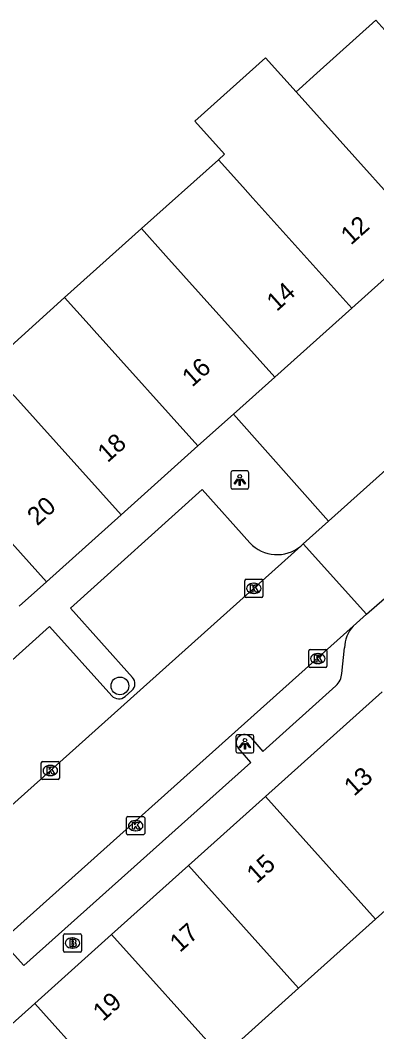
# Model space of a CAD drawing. Extents: x 162172 to 163187, y 382874 to 383684.
# Drawn here: x 162805.6 to 162825.2, y 383535.5 to 383591.4 of the extents above; entities that cross this region are included whole.
import ezdxf

# ---------------------------------------------------------------- set-up
doc = ezdxf.new("R2010")
doc.units = 0
for name, color, linetype in [('IMGEO_Boom', 7, 'Continuous'), ('IMGEO_Brandkraan', 7, 'Continuous'), ('IMGEO_Kolk', 7, 'Continuous'), ('IMGEO_Lichtpunt', 7, 'Continuous'), ('IMGEO_Pand', 7, 'Continuous'), ('IMGEO_Pand_nummerreeks', 7, 'Continuous'), ('IMGEO_Rijbaan_lokaal_open', 7, 'Continuous'), ('IMGEO_Voetpad_open', 7, 'Continuous')]:
    doc.layers.add(name, color=color, linetype=linetype)

msp = doc.modelspace()

# ---------------------------------------------------------------- linework, layer by layer
at = {"layer": 'IMGEO_Boom'}
msp.add_circle((162811.077, 383554.599), 0.489, dxfattribs=at)
at = {"layer": 'IMGEO_Brandkraan'}
for p, q in [((162807.957, 383539.978), (162807.957, 383540.83)), ((162808.032, 383540.904), (162808.884, 383540.904)), ((162808.445, 383540.684), (162808.47, 383540.684)), ((162808.958, 383540.83), (162808.958, 383539.978)), ((162808.468, 383540.124), (162808.443, 383540.124)), ((162808.884, 383539.904), (162808.032, 383539.904))]:
    msp.add_line(p, q, dxfattribs=at)
for points in [[(162807.957, 383539.978), (162807.957, 383540.83)], [(162808.032, 383540.904), (162808.884, 383540.904)], [(162808.958, 383540.83), (162808.958, 383539.978)], [(162808.305, 383540.604), (162808.305, 383540.204), (162808.518, 383540.204)], [(162808.536, 383540.604), (162808.305, 383540.604)], [(162808.484, 383540.523), (162808.43, 383540.523), (162808.43, 383540.447)], [(162808.43, 383540.447), (162808.483, 383540.447)], [(162808.492, 383540.371), (162808.43, 383540.371), (162808.43, 383540.29)], [(162808.43, 383540.29), (162808.492, 383540.29)], [(162808.884, 383539.904), (162808.032, 383539.904)]]:
    msp.add_lwpolyline(points, dxfattribs=at)
for centre, radius, start, end in [((162808.034, 383540.828), 0.0765, 91.552, 178.448), ((162808.034, 383540.828), 0.0765, 91.552, 178.448), ((162808.882, 383540.828), 0.0765, 1.552, 88.448), ((162808.882, 383540.828), 0.0765, 1.552, 88.448), ((162808.485, 383540.485), 0.0379, 267.8285, 90.9355), ((162808.493, 383540.33), 0.0404, 269.8759, 90.5077), ((162808.524, 383540.455), 0.251, 268.6676, 293.5347), ((162808.54, 383540.459), 0.145, 59.4692, 91.5367), ((162808.565, 383540.506), 0.0922, 285.5137, 58.1501), ((162808.57, 383540.314), 0.105, 301.3115, 78.989), ((162808.034, 383539.98), 0.0765, 181.552, 268.448), ((162808.034, 383539.98), 0.0765, 181.552, 268.448), ((162808.882, 383539.98), 0.0765, 271.552, 358.448), ((162808.882, 383539.98), 0.0765, 271.552, 358.448)]:
    msp.add_arc(centre, radius, start, end, dxfattribs=at)
for centre, major_axis, ratio, start_param, end_param in [((162808.444, 383540.404), (-0.387, 0.002), 0.722429, 4.712389, 7.853982), ((162808.469, 383540.404), (-0.39, 0.002), 0.717154, 1.570796, 4.712389)]:
    msp.add_ellipse(centre, major_axis=major_axis, ratio=ratio, start_param=start_param, end_param=end_param, dxfattribs=at)
at = {"layer": 'IMGEO_Kolk'}
for p, q in [((162817.97, 383559.558), (162817.97, 383560.41)), ((162818.045, 383560.484), (162818.897, 383560.484)), ((162818.458, 383560.264), (162818.483, 383560.264)), ((162818.971, 383560.41), (162818.971, 383559.558)), ((162818.481, 383559.704), (162818.456, 383559.704)), ((162818.897, 383559.484), (162818.045, 383559.484)), ((162821.5, 383555.683), (162821.5, 383556.535)), ((162821.575, 383556.609), (162822.427, 383556.609)), ((162821.988, 383556.389), (162822.013, 383556.389)), ((162822.501, 383556.535), (162822.501, 383555.683)), ((162822.011, 383555.829), (162821.986, 383555.829)), ((162822.427, 383555.609), (162821.575, 383555.609)), ((162806.737, 383549.503), (162806.737, 383550.355)), ((162806.812, 383550.429), (162807.664, 383550.429)), ((162807.225, 383550.209), (162807.25, 383550.209)), ((162807.738, 383550.355), (162807.738, 383549.503)), ((162807.248, 383549.649), (162807.223, 383549.649)), ((162807.664, 383549.429), (162806.812, 383549.429)), ((162811.52, 383547.384), (162812.372, 383547.384)), ((162811.445, 383546.458), (162811.445, 383547.31)), ((162811.933, 383547.164), (162811.958, 383547.164)), ((162812.446, 383547.31), (162812.446, 383546.458)), ((162812.372, 383546.384), (162811.52, 383546.384)), ((162811.956, 383546.604), (162811.931, 383546.604))]:
    msp.add_line(p, q, dxfattribs=at)
for points in [[(162817.97, 383559.558), (162817.97, 383560.41)], [(162818.045, 383560.484), (162818.897, 383560.484)], [(162818.291, 383560.184), (162818.414, 383560.184), (162818.414, 383560.033), (162818.544, 383560.184), (162818.708, 383560.184), (162818.562, 383560.033), (162818.715, 383559.784), (162818.563, 383559.784), (162818.478, 383559.948), (162818.414, 383559.881), (162818.414, 383559.784), (162818.291, 383559.784), (162818.291, 383560.184)], [(162818.971, 383560.41), (162818.971, 383559.558)], [(162818.897, 383559.484), (162818.045, 383559.484)], [(162821.5, 383555.683), (162821.5, 383556.535)], [(162821.575, 383556.609), (162822.427, 383556.609)], [(162821.821, 383556.309), (162821.944, 383556.309), (162821.944, 383556.158), (162822.074, 383556.309), (162822.238, 383556.309), (162822.092, 383556.158), (162822.245, 383555.909), (162822.093, 383555.909), (162822.008, 383556.073), (162821.944, 383556.006), (162821.944, 383555.909), (162821.821, 383555.909), (162821.821, 383556.309)], [(162822.501, 383556.535), (162822.501, 383555.683)], [(162822.427, 383555.609), (162821.575, 383555.609)], [(162806.737, 383549.503), (162806.737, 383550.355)], [(162806.812, 383550.429), (162807.664, 383550.429)], [(162807.738, 383550.355), (162807.738, 383549.503)], [(162807.058, 383550.129), (162807.181, 383550.129), (162807.181, 383549.978), (162807.311, 383550.129), (162807.475, 383550.129), (162807.329, 383549.978), (162807.482, 383549.729), (162807.33, 383549.729), (162807.245, 383549.893), (162807.181, 383549.826), (162807.181, 383549.729), (162807.058, 383549.729), (162807.058, 383550.129)], [(162807.664, 383549.429), (162806.812, 383549.429)], [(162811.52, 383547.384), (162812.372, 383547.384)], [(162811.445, 383546.458), (162811.445, 383547.31)], [(162811.766, 383547.084), (162811.889, 383547.084), (162811.889, 383546.933), (162812.019, 383547.084), (162812.183, 383547.084), (162812.037, 383546.933), (162812.19, 383546.684), (162812.038, 383546.684), (162811.953, 383546.848), (162811.889, 383546.781), (162811.889, 383546.684), (162811.766, 383546.684), (162811.766, 383547.084)], [(162812.446, 383547.31), (162812.446, 383546.458)], [(162812.372, 383546.384), (162811.52, 383546.384)]]:
    msp.add_lwpolyline(points, dxfattribs=at)
for centre, start, end in [((162818.047, 383560.408), 91.552, 178.448), ((162818.047, 383560.408), 91.552, 178.448), ((162818.895, 383560.408), 1.552, 88.448), ((162818.895, 383560.408), 1.552, 88.448), ((162818.047, 383559.56), 181.552, 268.448), ((162818.047, 383559.56), 181.552, 268.448), ((162818.895, 383559.56), 271.552, 358.448), ((162818.895, 383559.56), 271.552, 358.448), ((162821.577, 383556.533), 91.552, 178.448), ((162821.577, 383556.533), 91.552, 178.448), ((162822.425, 383556.533), 1.552, 88.448), ((162822.425, 383556.533), 1.552, 88.448), ((162821.577, 383555.685), 181.552, 268.448), ((162821.577, 383555.685), 181.552, 268.448), ((162822.425, 383555.685), 271.552, 358.448), ((162822.425, 383555.685), 271.552, 358.448), ((162806.814, 383550.353), 91.552, 178.448), ((162806.814, 383550.353), 91.552, 178.448), ((162807.662, 383550.353), 1.552, 88.448), ((162807.662, 383550.353), 1.552, 88.448), ((162806.814, 383549.505), 181.552, 268.448), ((162806.814, 383549.505), 181.552, 268.448), ((162807.662, 383549.505), 271.552, 358.448), ((162807.662, 383549.505), 271.552, 358.448), ((162811.522, 383547.308), 91.552, 178.448), ((162811.522, 383547.308), 91.552, 178.448), ((162812.37, 383547.308), 1.552, 88.448), ((162812.37, 383547.308), 1.552, 88.448), ((162811.522, 383546.46), 181.552, 268.448), ((162811.522, 383546.46), 181.552, 268.448), ((162812.37, 383546.46), 271.552, 358.448), ((162812.37, 383546.46), 271.552, 358.448)]:
    msp.add_arc(centre, 0.0765, start, end, dxfattribs=at)
for centre, major_axis, ratio, start_param, end_param in [((162818.457, 383559.984), (-0.387, 0.002), 0.722429, 4.712389, 7.853982), ((162818.482, 383559.984), (-0.39, 0.002), 0.717154, 1.570796, 4.712389), ((162821.987, 383556.109), (-0.387, 0.002), 0.722429, 4.712389, 7.853982), ((162822.012, 383556.109), (-0.39, 0.002), 0.717154, 1.570796, 4.712389), ((162807.224, 383549.929), (-0.387, 0.002), 0.722429, 4.712389, 7.853982), ((162807.249, 383549.929), (-0.39, 0.002), 0.717154, 1.570796, 4.712389), ((162811.932, 383546.884), (-0.387, 0.002), 0.722429, 4.712389, 7.853982), ((162811.957, 383546.884), (-0.39, 0.002), 0.717154, 1.570796, 4.712389)]:
    msp.add_ellipse(centre, major_axis=major_axis, ratio=ratio, start_param=start_param, end_param=end_param, dxfattribs=at)
at = {"layer": 'IMGEO_Lichtpunt'}
for p, q in [((162817.19, 383566.372), (162817.19, 383565.565)), ((162817.19, 383566.372), (162817.19, 383565.565)), ((162818.092, 383566.467), (162817.284, 383566.467)), ((162818.092, 383566.467), (162817.284, 383566.467)), ((162818.186, 383565.565), (162818.186, 383566.372)), ((162818.186, 383565.565), (162818.186, 383566.372)), ((162817.284, 383565.471), (162818.092, 383565.471)), ((162817.284, 383565.471), (162818.092, 383565.471)), ((162818.38, 383551.9), (162817.572, 383551.9)), ((162818.38, 383551.9), (162817.572, 383551.9)), ((162817.478, 383551.805), (162817.478, 383550.998)), ((162817.478, 383551.805), (162817.478, 383550.998)), ((162818.474, 383550.998), (162818.474, 383551.805)), ((162818.474, 383550.998), (162818.474, 383551.805)), ((162817.572, 383550.904), (162818.38, 383550.904)), ((162817.572, 383550.904), (162818.38, 383550.904))]:
    msp.add_line(p, q, dxfattribs=at)
for points in [[(162817.564, 383566.036), (162817.603, 383566.008), (162817.415, 383565.746), (162817.377, 383565.773), (162817.564, 383566.036)], [(162817.666, 383565.988), (162817.713, 383565.988), (162817.713, 383565.666), (162817.666, 383565.666), (162817.666, 383565.988)], [(162817.776, 383566.008), (162817.814, 383566.035), (162818.001, 383565.773), (162817.962, 383565.745), (162817.776, 383566.008)], [(162817.852, 383551.469), (162817.891, 383551.441), (162817.703, 383551.179), (162817.665, 383551.206), (162817.852, 383551.469)], [(162817.954, 383551.421), (162818.001, 383551.421), (162818.001, 383551.099), (162817.954, 383551.099), (162817.954, 383551.421)], [(162818.064, 383551.441), (162818.102, 383551.468), (162818.289, 383551.206), (162818.25, 383551.178), (162818.064, 383551.441)]]:
    msp.add_lwpolyline(points, dxfattribs=at)
for centre in [(162817.689, 383566.17), (162817.977, 383551.603)]:
    msp.add_circle(centre, 0.0994, dxfattribs=at)
for centre, start, end in [((162817.284, 383566.372), 90, 180), ((162817.284, 383566.372), 90, 180), ((162818.092, 383566.372), 0, 90), ((162818.092, 383566.372), 0, 90), ((162817.284, 383565.565), 180, 270), ((162817.284, 383565.565), 180, 270), ((162818.092, 383565.565), 270, 0), ((162818.092, 383565.565), 270, 360), ((162817.572, 383551.805), 90, 180), ((162817.572, 383551.805), 90, 180), ((162818.38, 383551.805), 0, 90), ((162818.38, 383551.805), 0, 90), ((162817.572, 383550.998), 180, 270), ((162817.572, 383550.998), 180, 270), ((162818.38, 383550.998), 270, 0), ((162818.38, 383550.998), 270, 360)]:
    msp.add_arc(centre, 0.0946, start, end, dxfattribs=at)
at = {"layer": 'IMGEO_Pand'}
for points in [[(162820.804, 383587.403), (162820.966, 383587.549), (162821.937, 383588.421), (162825.2, 383591.351), (162825.857, 383590.62)], [(162816.511, 383583.652), (162816.852, 383583.959), (162815.217, 383585.78), (162819.118, 383589.282), (162820.804, 383587.403)], [(162828.112, 383579.262), (162822.098, 383585.962), (162820.804, 383587.403)], [(162812.27, 383579.844), (162816.511, 383583.652)], [(162823.869, 383575.456), (162818.419, 383581.527), (162817.856, 383582.154), (162816.511, 383583.652)], [(162808.028, 383576.036), (162812.27, 383579.844)], [(162812.27, 383579.844), (162813.615, 383578.346), (162819.625, 383571.651)], [(162823.869, 383575.456), (162827.298, 383578.532)], [(162808.028, 383576.036), (162804.04, 383572.454)], [(162815.382, 383567.845), (162809.657, 383574.222), (162809.373, 383574.538), (162808.028, 383576.036)], [(162819.625, 383571.651), (162823.869, 383575.456)], [(162811.138, 383564.039), (162805.277, 383570.569), (162805.132, 383570.73), (162803.788, 383572.228), (162804.04, 383572.454)], [(162796.798, 383571.709), (162799.67, 383568.531), (162807.02, 383560.345)], [(162817.342, 383569.603), (162819.625, 383571.651)], [(162817.342, 383569.603), (162815.382, 383567.845)], [(162811.138, 383564.039), (162815.382, 383567.845)], [(162807.02, 383560.345), (162811.138, 383564.039)], [(162825.544, 383554.276), (162819.105, 383548.488)], [(162819.105, 383548.488), (162814.863, 383544.682)], [(162819.105, 383548.488), (162825.181, 383541.721)], [(162814.863, 383544.682), (162810.62, 383540.874)], [(162814.863, 383544.682), (162820.94, 383537.913)], [(162825.181, 383541.721), (162828.157, 383544.393)], [(162825.181, 383541.721), (162820.94, 383537.913)], [(162810.62, 383540.874), (162806.378, 383537.068)], [(162810.62, 383540.874), (162816.698, 383534.105)], [(162820.94, 383537.913), (162816.698, 383534.105)], [(162806.378, 383537.068), (162801.903, 383533.053)], [(162812.457, 383530.297), (162806.378, 383537.068)]]:
    msp.add_lwpolyline(points, dxfattribs=at)
at = {"layer": 'IMGEO_Rijbaan_lokaal_open'}
for points in [[(162822.586, 383563.697), (162832.592, 383572.652)], [(162821.194, 383562.443), (162822.586, 383563.697)], [(162821.053, 383562.317), (162821.194, 383562.443)], [(162824.683, 383558.558), (162821.194, 383562.443)], [(162821.053, 383562.317), (162784.698, 383529.72), (162780.973, 383526.23)], [(162824.683, 383558.558), (162826.095, 383559.798)], [(162823.948, 383557.9), (162824.683, 383558.558)], [(162799.554, 383535.964), (162801.184, 383537.501), (162823.948, 383557.9)]]:
    msp.add_lwpolyline(points, dxfattribs=at)
at = {"layer": 'IMGEO_Voetpad_open'}
for points in [[(162822.586, 383563.697), (162817.342, 383569.603)], [(162811.772, 383555.061), (162808.343, 383558.891), (162815.613, 383565.439), (162818.244, 383562.495)], [(162807.02, 383560.345), (162805.526, 383559.005)], [(162803.316, 383547.508), (162799.885, 383551.31), (162807.201, 383557.876), (162810.629, 383554.057)], [(162823.322, 383555.29), (162823.464, 383556.698)], [(162818.293, 383551.751), (162818.966, 383550.986), (162822.987, 383554.61)], [(162811.368, 383554.015), (162811.73, 383554.35)], [(162805.101, 383539.918), (162805.779, 383539.165), (162818.3, 383550.374), (162817.596, 383551.172)]]:
    msp.add_lwpolyline(points, dxfattribs=at)
for centre, radius, start, end in [((162819.744, 383563.906), 2.059, 223.2489, 309.4994), ((162825.464, 383556.591), 2.003, 139.1906, 176.9438), ((162822.32, 383555.361), 1.005, 311.6089, 355.9371), ((162811.43, 383554.724), 0.48, 308.6917, 44.547), ((162811.02, 383554.409), 0.526, 222.028, 311.4664), ((162817.945, 383551.462), 0.453, 39.7165, 219.7165)]:
    msp.add_arc(centre, radius, start, end, dxfattribs=at)

# ---------------------------------------------------------------- texts
at = {"layer": 'IMGEO_Pand_nummerreeks'}
for s, rotation, p in [('12', 41.8087, (162823.819, 383578.899)), ('14', 41.8087, (162819.729, 383575.238)), ('16', 41.8087, (162815.062, 383571.063)), ('18', 41.8087, (162810.397, 383566.891)), ('20', 41.8087, (162806.517, 383563.402)), ('13', 41.9182, (162824, 383548.475)), ('15', 41.9013, (162818.627, 383543.652)), ('17', 41.9013, (162814.384, 383539.846)), ('19', 41.9013, (162810.142, 383536.039))]:
    msp.add_text(s, height=1, rotation=rotation, dxfattribs=at).set_placement(p)

doc.saveas('drawing.dxf')
